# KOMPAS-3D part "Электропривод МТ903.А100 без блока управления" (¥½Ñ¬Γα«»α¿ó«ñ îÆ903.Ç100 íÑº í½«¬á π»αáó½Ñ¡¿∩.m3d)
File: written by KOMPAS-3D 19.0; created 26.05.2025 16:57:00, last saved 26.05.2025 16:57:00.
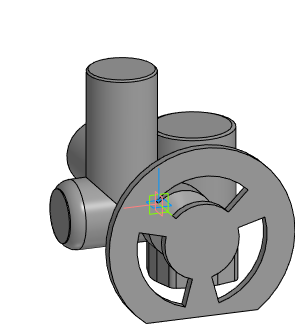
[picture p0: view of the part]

Document properties: Полное имя файла: E:\Dendor Работа Сачек\3D для проекитирвщиков\3.4 Электропривод МТ903.А\stp_Тип МТ903.А без блока управления\Электропривод МТ903.А100 без блока управления.m3d

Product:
- Part/product: Электропривод МТ903.А100 без блока управления

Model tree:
1. Операция без истории:1  (labels: Электропривод МТ903.А100 без блока управления)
